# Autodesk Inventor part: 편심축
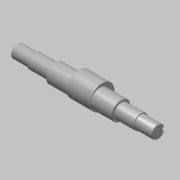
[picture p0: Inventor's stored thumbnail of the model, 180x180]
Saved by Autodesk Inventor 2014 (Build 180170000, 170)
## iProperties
Created: 2015-10
Part Number: 편심축
Document SubType Name: Modeling
Designer: mdu
Density: 7.86 g/cm^3
Material: 강철, 연강
Mass: 1327.93 g
Surface Area: 248.525 cm^2
Volume: 168.947 cm^3
Appearance: 강철
Author: mdu
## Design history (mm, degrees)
sketch "스케치1"
  geometry: L1 (-20.5, -41.331)-(-20.5, 32.669) reference; L2 (7.5, -30.031)-(7.5, 21.369) reference; L3 (135.5, -30.331)-(135.5, 21.669) reference; L4 (121.5, 21.369)-(121.5, -30.031) reference; L5 (184.5, -4.331)-(-57.5, -4.331); L6 (184.5, -4.331)-(184.5, 6.669); L7 (154.5, 8.169)-(121.5, 8.169); L8 (121.5, 8.169)-(121.5, 11.669); L9 (121.5, 11.669)-(7.5, 11.669); L10 (7.5, 11.669)-(7.5, 8.169); L11 (7.5, 8.169)-(-27.5, 8.169); L12 (-27.5, 8.169)-(-27.5, 6.669); L13 (-27.5, 6.669)-(-57.5, 6.669); L14 (-57.5, 6.669)-(-57.5, -4.331); L15 (154.5, 8.169)-(154.5, 6.669); L16 (154.5, 6.669)-(184.5, 6.669); C1 r 32.5 at (64.5, -4.331) reference; 1 further point
  constraints: 24 end point, 8 perpendicular, 5 point on line, 3 parallel, 2 collinear
  dimensions: "d1" = 25 diameter of L11 L5; "d2" = 32 diameter of L9 L5; "d3" = 22 diameter of L13 L5; "d4" = 35 distance of L10.end L11.end; "d5" = 30 distance of L12.end L13.end; "d15" = 33 distance of L7.start L7.end; "d26" = 30 distance of L15.end L6.end
revolve "회전1" sketch "스케치1" stored, may be unused: angle "d6" = 90 deg
node "작업 평면1"
sketch "스케치2"
  geometry: C1 r 16 at (0, 0) reference; C2 r 16 at (0, 0) reference; C3 r 20.75 at (0, 4); C4 r 16 at (0, 0) reference; 1 further point
  constraints: 1 centre point, 1 vertical alignment
  dimensions: "d8" = 41.5 diameter of C3; "d25" = 4 distance of C3.centre C1.centre
extrude "돌출1" join sketch "스케치2" stored distance "d9" = 40; taper "d10" = 0 deg
chamfer "모따기1" distance "d11" = 1; stored, may be unused: second distance "d12" = 2, angle "d13" = 45 deg
node "작업 평면2"
sketch "스케치3"
  geometry: L1 (-15, -10)-(-15, 10) reference; L2 (-15, 3)-(0, 3); L3 (0, -3)-(-15, -3); A1 r 3 centre (0, 0) between (0, -3) and (0, 3); 2 further points
  constraints: 4 end point, 2 perpendicular, 2 point on circle, 2 point on line, 2 tangent, 1 centre point, 1 horizontal alignment, 1 midpoint
  dimensions: "d16" = 18 dimension on A1 L1; "d17" = 6 distance between parallel lines of L3 L2
extrude "돌출2" cut sketch "스케치3" distance "d18" = 3.5; taper "d19" = 0 deg
node "작업 평면3"
node "솔리드1"
mirror "대칭1"
node "참조1"
node "참조2"
node "참조3"
node "참조4"
node "참조5"
node "투영된 루프1"
